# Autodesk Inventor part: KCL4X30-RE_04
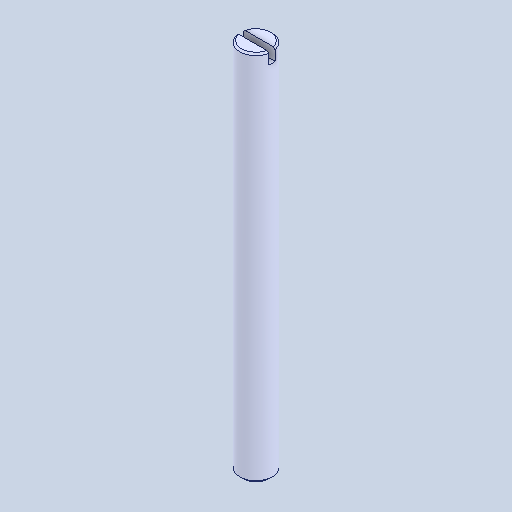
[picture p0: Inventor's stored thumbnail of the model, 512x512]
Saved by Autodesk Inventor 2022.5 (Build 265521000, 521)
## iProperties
Created: 2024-08
Part Number: KCL4X30-RE_04
Material: 一般
Document SubType Name: Modeling
Designer: ImaoCorp
Density: 1 g/cm^3
Appearance: 既定
Author: ImaoCorp
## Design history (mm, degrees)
feature "KCL4X30-RE_04"
node "ソリッド1"
